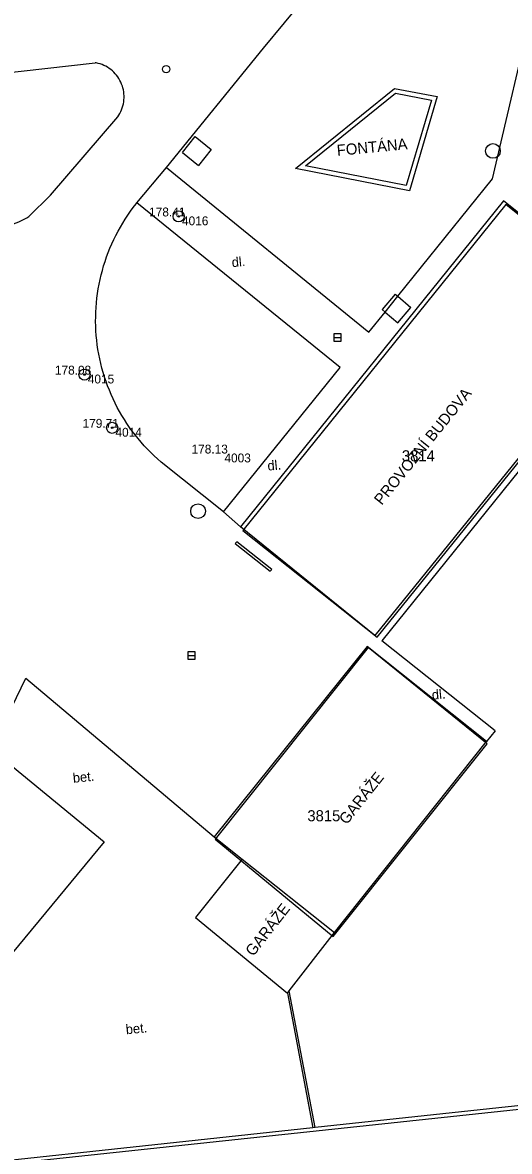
# Model space of a CAD drawing. Extents: x -540150 to -533593, y -1185082 to -1180066.
# Drawn here: x -536935.2 to -536902.3, y -1184365.5 to -1184289.1 of the extents above; entities that cross this region are included whole.
import ezdxf

# ---------------------------------------------------------------- set-up
doc = ezdxf.new("R2010")
doc.units = 0
for name, color, linetype in [('KN_HRAN_PARCEL', 7, 'Continuous'), ('KN_PARC_Č', 7, 'Continuous'), ('Vrstva 10', 7, 'Continuous'), ('Vrstva 11', 7, 'Continuous'), ('Vrstva 21', 7, 'Continuous'), ('Vrstva 22', 7, 'Continuous'), ('Vrstva 23', 7, 'Continuous'), ('Vrstva 27', 7, 'Continuous'), ('Vrstva 28', 7, 'Continuous'), ('Vrstva 40', 7, 'Continuous'), ('Vrstva 41', 7, 'Continuous'), ('Vrstva 5', 7, 'Continuous'), ('Vrstva 7', 7, 'Continuous')]:
    doc.layers.add(name, color=color, linetype=linetype)

msp = doc.modelspace()

# ---------------------------------------------------------------- linework, layer by layer
at = {"layer": 'KN_HRAN_PARCEL'}
for p, q in [((-536902.552, -1184301.441), (-536920.332, -1184323.481)), ((-536893.532, -1184308.751), (-536902.552, -1184301.441)), ((-536911.252, -1184330.711), (-536893.532, -1184308.751)), ((-536920.332, -1184323.481), (-536911.252, -1184330.711)), ((-536911.862, -1184331.411), (-536922.212, -1184344.371)), ((-536903.822, -1184337.921), (-536911.862, -1184331.411)), ((-536914.232, -1184350.951), (-536903.822, -1184337.921)), ((-536922.212, -1184344.371), (-536914.232, -1184350.951)), ((-536872.352, -1184359.541), (-536950.452, -1184367.871))]:
    msp.add_line(p, q, dxfattribs=at)
at = {"layer": 'Vrstva 10'}
for p, q in [((-536918.942, -1184290.861), (-536903.422, -1184272.031)), ((-536925.502, -1184298.941), (-536918.942, -1184290.861)), ((-536941.282, -1184293.091), (-536930.322, -1184291.841)), ((-536933.332, -1184300.811), (-536928.792, -1184295.501)), ((-536927.502, -1184301.331), (-536925.502, -1184298.941)), ((-536934.802, -1184302.241), (-536933.332, -1184300.811)), ((-536921.652, -1184322.221), (-536925.862, -1184318.861)), ((-536921.652, -1184322.221), (-536920.502, -1184323.241)), ((-536937.342, -1184338.281), (-536935.002, -1184333.481)), ((-536935.002, -1184333.481), (-536922.272, -1184344.211)), ((-536917.322, -1184354.781), (-536915.591, -1184363.902)), ((-536915.442, -1184363.886), (-536917.2, -1184354.624))]:
    msp.add_line(p, q, dxfattribs=at)
for points in [[(-536928.792, -1184295.501), (-536928.717, -1184295.387), (-536928.648, -1184295.268), (-536928.586, -1184295.146), (-536928.532, -1184295.021), (-536928.485, -1184294.892), (-536928.445, -1184294.761), (-536928.414, -1184294.628), (-536928.39, -1184294.493), (-536928.374, -1184294.357), (-536928.366, -1184294.22), (-536928.366, -1184294.083), (-536928.374, -1184293.947), (-536928.39, -1184293.811), (-536928.414, -1184293.676), (-536928.446, -1184293.543), (-536928.482, -1184293.421), (-536928.532, -1184293.283), (-536928.587, -1184293.157), (-536928.648, -1184293.035), (-536928.717, -1184292.917), (-536928.793, -1184292.803), (-536928.875, -1184292.693), (-536928.963, -1184292.588), (-536929.057, -1184292.489), (-536929.157, -1184292.396), (-536929.263, -1184292.308), (-536929.373, -1184292.227), (-536929.487, -1184292.152), (-536929.606, -1184292.084), (-536929.729, -1184292.023), (-536929.855, -1184291.97), (-536929.984, -1184291.924), (-536930.115, -1184291.885), (-536930.249, -1184291.854), (-536930.322, -1184291.841)], [(-536930.244, -1184310.305), (-536930.267, -1184309.988), (-536930.281, -1184309.67), (-536930.288, -1184309.352), (-536930.286, -1184309.034), (-536930.277, -1184308.716), (-536930.26, -1184308.399), (-536930.234, -1184308.082), (-536930.201, -1184307.765), (-536930.16, -1184307.45), (-536930.11, -1184307.136), (-536930.053, -1184306.823), (-536929.988, -1184306.511), (-536929.915, -1184306.202), (-536929.835, -1184305.894), (-536929.747, -1184305.588), (-536929.651, -1184305.285), (-536929.547, -1184304.984), (-536929.436, -1184304.686), (-536929.318, -1184304.391), (-536929.192, -1184304.099), (-536929.059, -1184303.81), (-536928.918, -1184303.525), (-536928.771, -1184303.243), (-536928.616, -1184302.965), (-536928.454, -1184302.691), (-536928.286, -1184302.421), (-536928.111, -1184302.156), (-536927.929, -1184301.895), (-536927.741, -1184301.638), (-536927.546, -1184301.387), (-536927.502, -1184301.331)], [(-536936.232, -1184302.851), (-536936.041, -1184302.799), (-536935.852, -1184302.74), (-536935.665, -1184302.673), (-536935.482, -1184302.598), (-536935.301, -1184302.516), (-536935.124, -1184302.427), (-536934.951, -1184302.331), (-536934.802, -1184302.241)], [(-536925.862, -1184318.861), (-536926.101, -1184318.651), (-536926.335, -1184318.435), (-536926.563, -1184318.214), (-536926.786, -1184317.987), (-536927.002, -1184317.754), (-536927.213, -1184317.516), (-536927.418, -1184317.273), (-536927.617, -1184317.024), (-536927.809, -1184316.771), (-536927.995, -1184316.513), (-536928.175, -1184316.25), (-536928.347, -1184315.983), (-536928.513, -1184315.712), (-536928.672, -1184315.436), (-536928.824, -1184315.157), (-536928.969, -1184314.874), (-536929.107, -1184314.587), (-536929.238, -1184314.297), (-536929.361, -1184314.004), (-536929.477, -1184313.708), (-536929.585, -1184313.408), (-536929.686, -1184313.107), (-536929.779, -1184312.803), (-536929.865, -1184312.496), (-536929.942, -1184312.188), (-536930.012, -1184311.878), (-536930.075, -1184311.566), (-536930.129, -1184311.252), (-536930.175, -1184310.938), (-536930.214, -1184310.622), (-536930.244, -1184310.305)]]:
    msp.add_lwpolyline(points, dxfattribs=at)
at = {"layer": 'Vrstva 11'}
for p, q in [((-536903.462, -1184299.701), (-536899.352, -1184282.131)), ((-536916.78, -1184298.99), (-536910.081, -1184293.59)), ((-536916.092, -1184298.82), (-536910.001, -1184293.91)), ((-536910.081, -1184293.59), (-536907.184, -1184294.138)), ((-536910.001, -1184293.91), (-536907.565, -1184294.37)), ((-536907.565, -1184294.37), (-536909.282, -1184300.155)), ((-536907.184, -1184294.138), (-536909.073, -1184300.501)), ((-536924.422, -1184297.911), (-536923.562, -1184296.831)), ((-536923.562, -1184296.831), (-536922.482, -1184297.721)), ((-536924.422, -1184297.911), (-536923.342, -1184298.801)), ((-536922.482, -1184297.721), (-536923.342, -1184298.801)), ((-536925.502, -1184298.941), (-536911.822, -1184310.081)), ((-536909.073, -1184300.501), (-536916.78, -1184298.99)), ((-536909.282, -1184300.155), (-536916.092, -1184298.82)), ((-536909.862, -1184307.647), (-536903.462, -1184299.701)), ((-536913.762, -1184312.451), (-536927.502, -1184301.331)), ((-536892.785, -1184308.446), (-536910.943, -1184330.95)), ((-536909.862, -1184309.441), (-536908.982, -1184308.401)), ((-536910.717, -1184308.708), (-536909.862, -1184309.441)), ((-536921.652, -1184322.221), (-536913.762, -1184312.451)), ((-536920.742, -1184324.246), (-536920.842, -1184324.371)), ((-536920.842, -1184324.371), (-536918.481, -1184326.248)), ((-536918.381, -1184326.123), (-536920.742, -1184324.246)), ((-536918.381, -1184326.123), (-536918.481, -1184326.248)), ((-536903.28, -1184337.045), (-536910.943, -1184330.95)), ((-536903.28, -1184337.045), (-536903.853, -1184337.765)), ((-536937.342, -1184338.281), (-536929.702, -1184344.541)), ((-536929.702, -1184344.541), (-536935.943, -1184352.092))]:
    msp.add_line(p, q, dxfattribs=at)
for points in [[(-536911.822, -1184310.081), (-536910.717, -1184308.708), (-536909.862, -1184307.647)], [(-536910.032, -1184307.501), (-536910.912, -1184308.541), (-536910.717, -1184308.708)], [(-536910.032, -1184307.501), (-536909.862, -1184307.647), (-536908.982, -1184308.401)]]:
    msp.add_lwpolyline(points, dxfattribs=at)
at = {"layer": 'Vrstva 21'}
for centre, radius in [((-536924.672, -1184302.241), 0.375), ((-536924.672, -1184302.241), 0.05), ((-536931.042, -1184312.941), 0.375), ((-536931.042, -1184312.941), 0.05), ((-536929.172, -1184316.541), 0.375), ((-536929.172, -1184316.541), 0.05)]:
    msp.add_circle(centre, radius, dxfattribs=at)
at = {"layer": 'Vrstva 27'}
for p, q in [((-536914.182, -1184310.441), (-536913.682, -1184310.441)), ((-536924.062, -1184331.951), (-536923.562, -1184331.951))]:
    msp.add_line(p, q, dxfattribs=at)
for points in [[(-536914.182, -1184310.691), (-536913.682, -1184310.691), (-536913.682, -1184310.191), (-536914.182, -1184310.191)], [(-536924.062, -1184332.201), (-536923.562, -1184332.201), (-536923.562, -1184331.701), (-536924.062, -1184331.701)]]:
    msp.add_lwpolyline(points, close=True, dxfattribs=at)
for centre in [(-536903.422, -1184297.811), (-536923.362, -1184322.181)]:
    msp.add_circle(centre, 0.5, dxfattribs=at)
at = {"layer": 'Vrstva 28'}
msp.add_circle((-536925.522, -1184292.281), 0.25, dxfattribs=at)
at = {"layer": 'Vrstva 5'}
for p, q in [((-536902.702, -1184301.181), (-536920.502, -1184323.241)), ((-536893.572, -1184308.511), (-536911.397, -1184330.588)), ((-536911.397, -1184330.588), (-536920.502, -1184323.241)), ((-536911.926, -1184331.344), (-536922.272, -1184344.211)), ((-536903.853, -1184337.765), (-536911.926, -1184331.344)), ((-536914.134, -1184350.691), (-536903.853, -1184337.765))]:
    msp.add_line(p, q, dxfattribs=at)
for points in [[(-536899.056, -1184304.123), (-536902.702, -1184301.181)], [(-536922.272, -1184344.211), (-536920.389, -1184345.717), (-536914.134, -1184350.691)], [(-536920.389, -1184345.717), (-536923.533, -1184349.673), (-536917.322, -1184354.781), (-536917.2, -1184354.624), (-536914.134, -1184350.691)]]:
    msp.add_lwpolyline(points, dxfattribs=at)
at = {"layer": 'Vrstva 7'}
msp.add_lwpolyline([(-536872.574, -1184359.281), (-536872.911, -1184359.32), (-536915.442, -1184363.886), (-536915.591, -1184363.902), (-536949.139, -1184367.504), (-536975.472, -1184370.331)], dxfattribs=at)

# ---------------------------------------------------------------- texts
at = {"layer": 'KN_PARC_Č'}
for s, p in [('3814', (-536909.582, -1184318.811)), ('3815', (-536915.972, -1184343.161))]:
    msp.add_text(s, height=0.75, dxfattribs=at).set_placement(p)
at = {"layer": 'Vrstva 22'}
for s, p in [('178.41 ', (-536926.672, -1184302.241)), ('178.08 ', (-536933.042, -1184312.941)), ('179.71 ', (-536931.172, -1184316.541)), ('178.13 ', (-536923.802, -1184318.281))]:
    msp.add_text(s, height=0.6, dxfattribs=at).set_placement(p)
at = {"layer": 'Vrstva 23'}
for s, p in [(' 4016', (-536924.672, -1184302.841)), (' 4015', (-536931.042, -1184313.541)), (' 4014', (-536929.172, -1184317.141)), (' 4003', (-536921.802, -1184318.881))]:
    msp.add_text(s, height=0.6, dxfattribs=at).set_placement(p)
at = {"layer": 'Vrstva 40'}
for s, p in [('dl.', (-536921.057, -1184305.677)), ('dl.', (-536918.638, -1184319.443)), ('dl.', (-536907.522, -1184334.938)), ('bet.', (-536931.801, -1184340.557)), ('bet.', (-536928.222, -1184357.573))]:
    msp.add_text(s, height=0.65, rotation=5.42156, dxfattribs=at).set_placement(p)
at = {"layer": 'Vrstva 41'}
for s, rotation, p in [('FONTÁNA', 5.42156, (-536913.944, -1184298.148)), ('PROVOZNÍ BUDOVA', 51.10028, (-536910.941, -1184321.821)), ('GARÁŽE', 51.50218, (-536913.31, -1184343.435)), ('GARÁŽE', 52.06494, (-536919.633, -1184352.346))]:
    msp.add_text(s, height=0.75, rotation=rotation, dxfattribs=at).set_placement(p)

doc.saveas('drawing.dxf')
